(* Logix 5000 project; controller Demo_E300 vendor 1 type 14 code 164 rev 35.11; software revision 35.00 *)

TASK MainTask (continuous, watchdog 500 ms) : MainProgram

MODULES
   Local : vendor 1 type 14 code 164 (ICP 0, rev 35.11)
      Enet : 1756-EN2T (ICP 1, Ethernet 192.168.1.1, rev 11.1)   // Ethernet Card for E300 Modules
         Motor_0 : 193-ECM-ETR (Ethernet 192.168.1.10, rev 6.1, StandardDataDriven RPI 100 ms)
END_MODULES

TYPE Motor_Data :
STRUCT
   PB_Start : BOOL;
   PB_Stop : BOOL;
   Running : BOOL;
   Voltage : REAL;
   Current : REAL;
   Power : REAL;
   Overload_Trip : BOOL;
   Phase_LossTrip : BOOL;
   Ground_Fault_Current_Trip : BOOL;
   Stall_Trip : BOOL;
   Trip_Reset : BOOL;
   Load_Percent : REAL;
END_STRUCT
END_TYPE

ADD_ON_INSTRUCTION E300_SIM   (* revision 1.0, vendor Rockwell Automation Mexico *)
// Add On instruction to simulate an E300 operation
// Revision note:
// Initial Version
VAR_INPUT
   E300_Motor_Start : BOOL; {required}
   E300_Motor_Stop : BOOL; {required}
END_VAR
VAR_OUTPUT
   E300_Motor_Run : BOOL; {access Read Only, required}
END_VAR
VAR_IN_OUT
   InputE300INP : AB:E300:I:3; {required}
   ConfigE300CFG : AB:E300:C:3; {required}
END_VAR
VAR_INPUT
   E300_Load : REAL;
END_VAR
VAR_IN_OUT
   OutputE300OUT : AB:E300:O:1; {required}
END_VAR
VAR_INPUT
   E300_Simulate_OverloadTrip : BOOL; {required}
   E300_Simulate_PhaseLossTrip : BOOL;
   E300_Simulate_GroundFaultCurrentTrip : BOOL;
   E300_Simulate_StallTrip : BOOL;
   E300_Simulate_JamTrip : BOOL;
   E300_Simulate_UnderloadTrip : BOOL;
   E300_Simulate_CurrentImbalanceTrip : BOOL;
   E300_Simulate_L1UnderCurrentTrip : BOOL;
   E300_Simulate_L2UnderCurrentTrip : BOOL;
   E300_Simulate_L3UnderCurrentTrip : BOOL;
   E300_Simulate_L1OverCurrentTrip : BOOL;
   E300_Simulate_L2OverCurrentTrip : BOOL;
   E300_Simulate_L3OverCurrentTrip : BOOL;
   E300_Simulate_L1LineLossTrip : BOOL;
   E300_Simulate_L2LineLossTrip : BOOL;
   E300_Simulate_L3LineLossTrip : BOOL;
   Trip_Reset : BOOL; {required}
   E300_Percent_Load : REAL; {access None, required}
END_VAR
VAR
   E300_Timer_2 : TIMER := (PRE := 4000); {access None}
   E300_Timer_3 : TIMER := (PRE := 19000); {access None}
   E300_Speed : DINT; {access None}
   E300_Timer_1 : TIMER := (PRE := 100); {access None}
   E300_Random : REAL; {access None}
   E300_Factor_1 : REAL; {access None}
   E300_Factor_2 : REAL; {access None}
   E300_Factor_3 : REAL; {access None}
   E300_Current : REAL; {access None}
   E300_Current_Generated : REAL; {access None}
   E300_Seconds : TIMER := (PRE := 6000); {access None}
   E300_Minutes : COUNTER := (PRE := 60); {access None}
   E300_Hours : COUNTER := (PRE := 100000); {access None}
   E300_Torque_Generated : REAL; {access None}
   E300_HP_Generated : REAL; {access None}
   E300_FP_Generated : REAL; {access None}
   E300_Speed_Simulated : DINT; {access None}
   E300_Current_Scalated : DINT; {access None}
   E300_Curve_Amps : REAL[28]; {access None}
   E300_FGEN_AMPS : DINT; {access None}
   E300_Voltage_Generated : DINT; {access None}
   E300_Torque_Scalated : REAL; {access None}
   E300_Curve_Torque : REAL[28]; {access None}
   E300_FGEN_Torque : REAL; {access None}
   E300_Curve_FP : REAL[28]; {access None}
   E300_FGEN_PF : REAL; {access None}
END_VAR

ROUTINE Logic   (* ladder *)
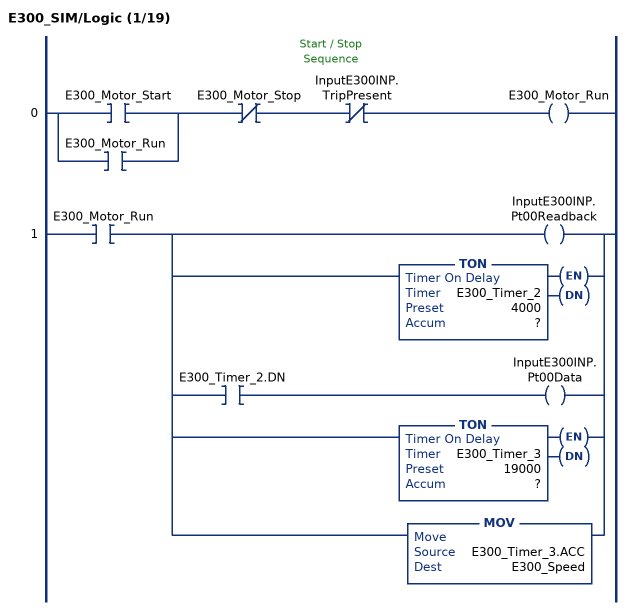
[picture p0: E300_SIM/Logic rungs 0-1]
   // Start / Stop
   // Sequence
   0: [XIC(E300_Motor_Start) ,XIC(E300_Motor_Run) ]XIO(E300_Motor_Stop)XIO(InputE300INP.TripPresent)OTE(E300_Motor_Run);
   1: XIC(E300_Motor_Run)[OTE(InputE300INP.Pt00Readback) ,TON(E300_Timer_2,?,?) ,XIC(E300_Timer_2.DN) OTE(InputE300INP.Pt00Data) ,TON(E300_Timer_3,?,?) ,MOV(E300_Timer_3.ACC,E300_Speed) ];
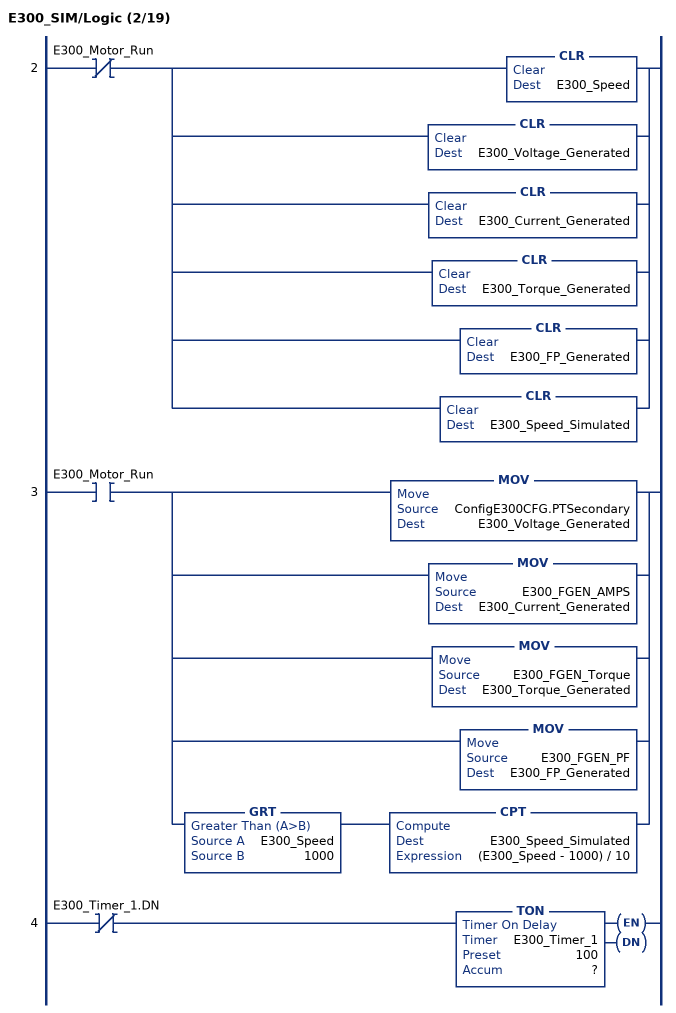
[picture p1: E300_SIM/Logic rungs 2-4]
   2: XIO(E300_Motor_Run)[CLR(E300_Speed) ,CLR(E300_Voltage_Generated) ,CLR(E300_Current_Generated) ,CLR(E300_Torque_Generated) ,CLR(E300_FP_Generated) ,CLR(E300_Speed_Simulated) ];
   3: XIC(E300_Motor_Run)[MOV(ConfigE300CFG.PTSecondary,E300_Voltage_Generated) ,MOV(E300_FGEN_AMPS,E300_Current_Generated) ,MOV(E300_FGEN_Torque,E300_Torque_Generated) ,MOV(E300_FGEN_PF,E300_FP_Generated) ,GRT(E300_Speed,1000) CPT(E300_Speed_Simulated,(E300_Speed - 1000) / 10) ];
   4: XIO(E300_Timer_1.DN)TON(E300_Timer_1,?,?);
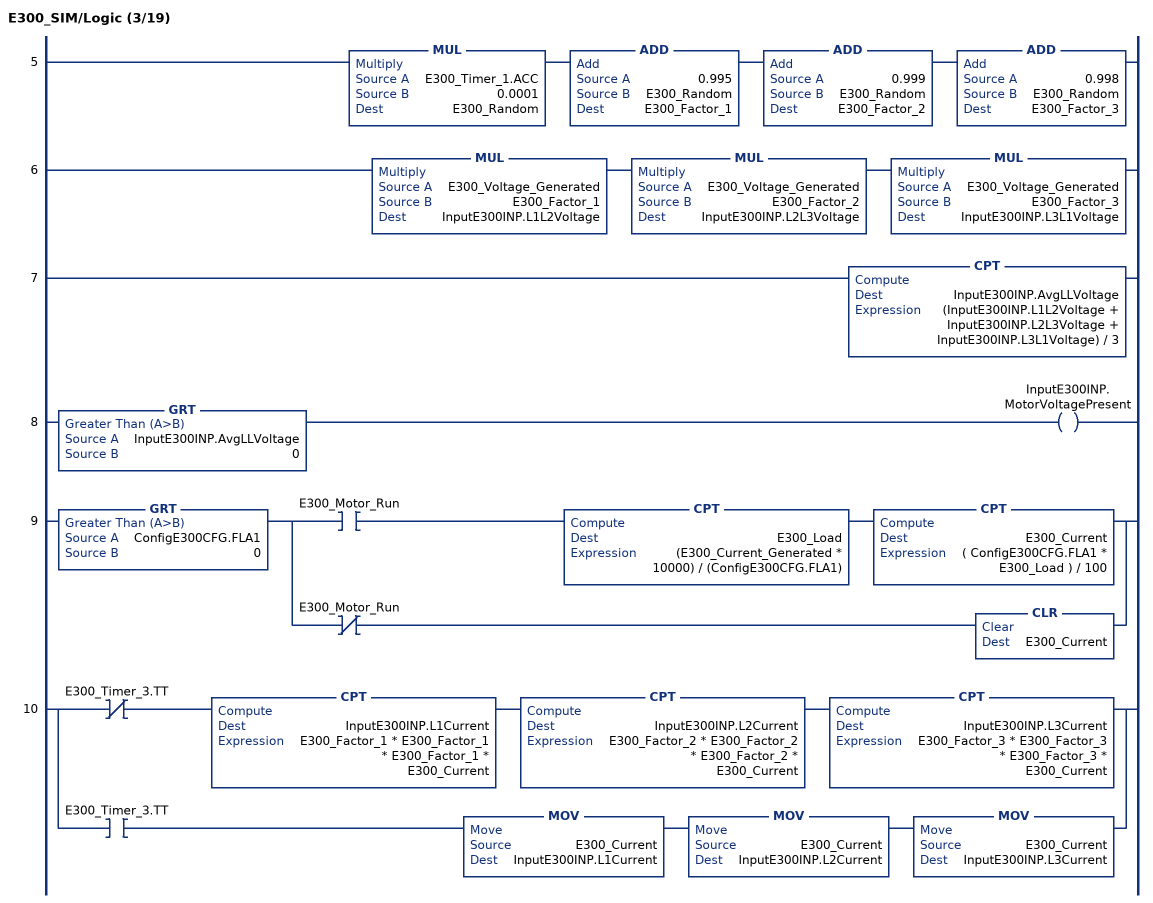
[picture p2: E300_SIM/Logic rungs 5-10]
   5: MUL(E300_Timer_1.ACC,0.0001,E300_Random)ADD(0.995,E300_Random,E300_Factor_1)ADD(0.999,E300_Random,E300_Factor_2)ADD(0.998,E300_Random,E300_Factor_3);
   6: MUL(E300_Voltage_Generated,E300_Factor_1,InputE300INP.L1L2Voltage)MUL(E300_Voltage_Generated,E300_Factor_2,InputE300INP.L2L3Voltage)MUL(E300_Voltage_Generated,E300_Factor_3,InputE300INP.L3L1Voltage);
   7: CPT(InputE300INP.AvgLLVoltage,(InputE300INP.L1L2Voltage + InputE300INP.L2L3Voltage + InputE300INP.L3L1Voltage) / 3);
   8: GRT(InputE300INP.AvgLLVoltage,0)OTE(InputE300INP.MotorVoltagePresent);
   9: GRT(ConfigE300CFG.FLA1,0)[XIC(E300_Motor_Run) CPT(E300_Load,(E300_Current_Generated * 10000) / (ConfigE300CFG.FLA1)) CPT(E300_Current,( ConfigE300CFG.FLA1 * E300_Load ) / 100) ,XIO(E300_Motor_Run) CLR(E300_Current) ];
   10: [XIO(E300_Timer_3.TT) CPT(InputE300INP.L1Current,E300_Factor_1 * E300_Factor_1 * E300_Factor_1 * E300_Current) CPT(InputE300INP.L2Current,E300_Factor_2 * E300_Factor_2 * E300_Factor_2 * E300_Current) CPT(InputE300INP.L3Current,E300_Factor_3 * E300_Factor_3 * E300_Factor_3 * E300_Current) ,XIC(E300_Timer_3.TT) MOV(E300_Current,InputE300INP.L1Current) MOV(E300_Current,InputE300INP.L2Current) MOV(E300_Current,InputE300INP.L3Current) ];
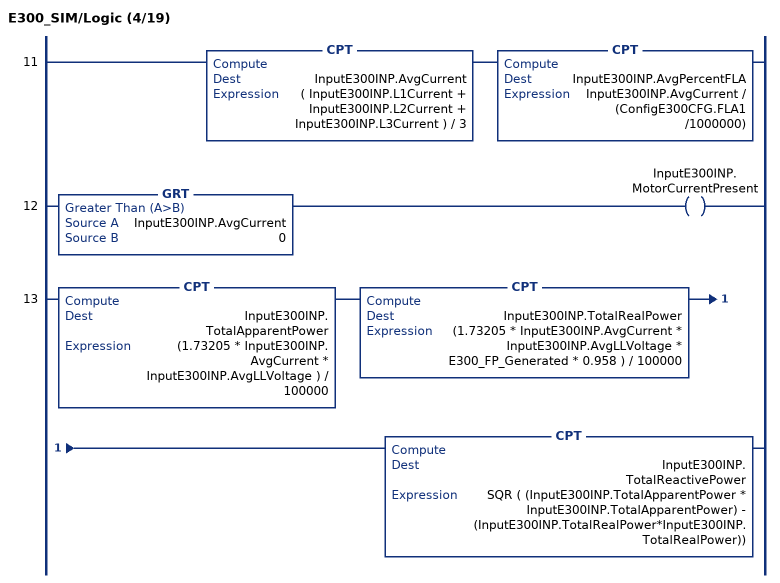
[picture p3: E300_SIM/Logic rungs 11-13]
   11: CPT(InputE300INP.AvgCurrent,( InputE300INP.L1Current + InputE300INP.L2Current + InputE300INP.L3Current ) / 3)CPT(InputE300INP.AvgPercentFLA,InputE300INP.AvgCurrent / (ConfigE300CFG.FLA1 /1000000));
   12: GRT(InputE300INP.AvgCurrent,0)OTE(InputE300INP.MotorCurrentPresent);
   13: CPT(InputE300INP.TotalApparentPower,(1.73205 * InputE300INP.AvgCurrent * InputE300INP.AvgLLVoltage ) / 100000)CPT(InputE300INP.TotalRealPower,(1.73205 * InputE300INP.AvgCurrent * InputE300INP.AvgLLVoltage * E300_FP_Generated * 0.958 ) / 100000)CPT(InputE300INP.TotalReactivePower,SQR ( (InputE300INP.TotalApparentPower * InputE300INP.TotalApparentPower) - (InputE300INP.TotalRealPower*InputE300INP.TotalRealPower)));
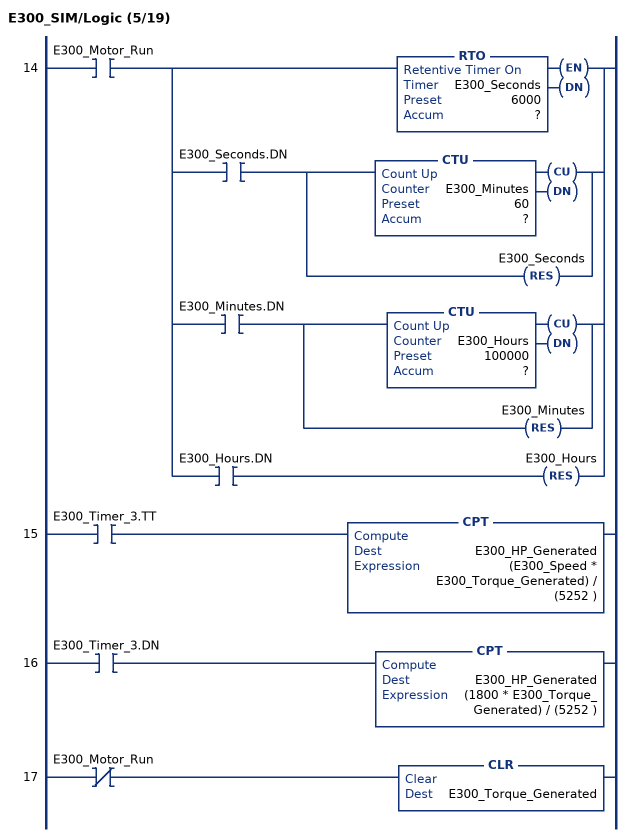
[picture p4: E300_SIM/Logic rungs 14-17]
   14: XIC(E300_Motor_Run)[RTO(E300_Seconds,?,?) ,XIC(E300_Seconds.DN) [CTU(E300_Minutes,?,?) ,RES(E300_Seconds) ] ,XIC(E300_Minutes.DN) [CTU(E300_Hours,?,?) ,RES(E300_Minutes) ] ,XIC(E300_Hours.DN) RES(E300_Hours) ];
   15: XIC(E300_Timer_3.TT)CPT(E300_HP_Generated,(E300_Speed * E300_Torque_Generated) / (5252 ));
   16: XIC(E300_Timer_3.DN)CPT(E300_HP_Generated,(1800 * E300_Torque_Generated) / (5252 ));
   17: XIO(E300_Motor_Run)CLR(E300_Torque_Generated);
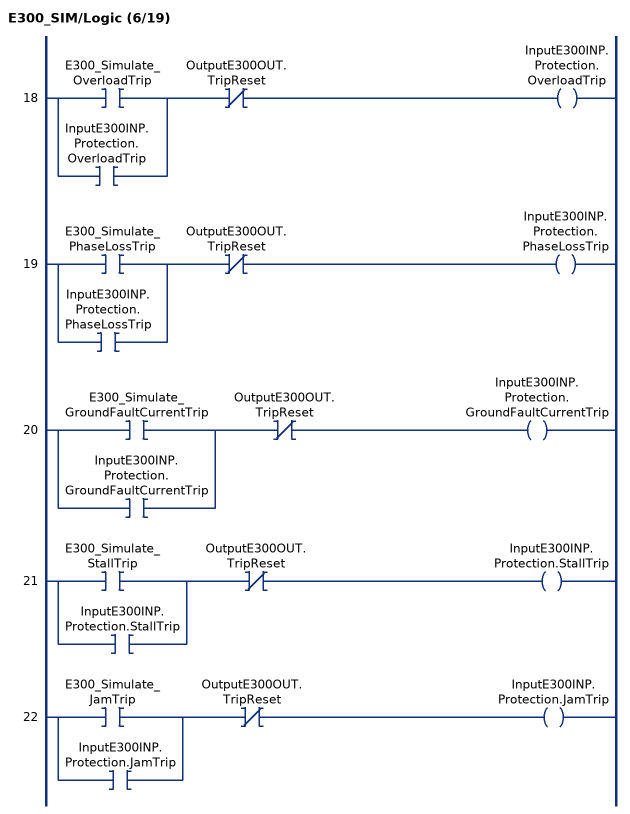
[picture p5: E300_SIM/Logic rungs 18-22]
   18: [XIC(E300_Simulate_OverloadTrip) ,XIC(InputE300INP.Protection.OverloadTrip) ]XIO(OutputE300OUT.TripReset)OTE(InputE300INP.Protection.OverloadTrip);
   19: [XIC(E300_Simulate_PhaseLossTrip) ,XIC(InputE300INP.Protection.PhaseLossTrip) ]XIO(OutputE300OUT.TripReset)OTE(InputE300INP.Protection.PhaseLossTrip);
   20: [XIC(E300_Simulate_GroundFaultCurrentTrip) ,XIC(InputE300INP.Protection.GroundFaultCurrentTrip) ]XIO(OutputE300OUT.TripReset)OTE(InputE300INP.Protection.GroundFaultCurrentTrip);
   21: [XIC(E300_Simulate_StallTrip) ,XIC(InputE300INP.Protection.StallTrip) ]XIO(OutputE300OUT.TripReset)OTE(InputE300INP.Protection.StallTrip);
   22: [XIC(E300_Simulate_JamTrip) ,XIC(InputE300INP.Protection.JamTrip) ]XIO(OutputE300OUT.TripReset)OTE(InputE300INP.Protection.JamTrip);
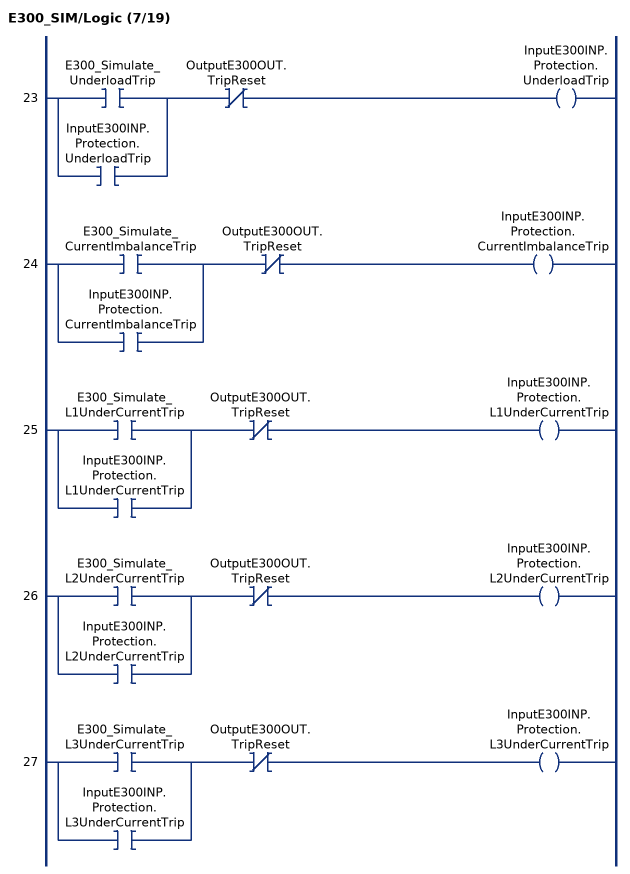
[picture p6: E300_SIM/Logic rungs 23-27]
   23: [XIC(E300_Simulate_UnderloadTrip) ,XIC(InputE300INP.Protection.UnderloadTrip) ]XIO(OutputE300OUT.TripReset)OTE(InputE300INP.Protection.UnderloadTrip);
   24: [XIC(E300_Simulate_CurrentImbalanceTrip) ,XIC(InputE300INP.Protection.CurrentImbalanceTrip) ]XIO(OutputE300OUT.TripReset)OTE(InputE300INP.Protection.CurrentImbalanceTrip);
   25: [XIC(E300_Simulate_L1UnderCurrentTrip) ,XIC(InputE300INP.Protection.L1UnderCurrentTrip) ]XIO(OutputE300OUT.TripReset)OTE(InputE300INP.Protection.L1UnderCurrentTrip);
   26: [XIC(E300_Simulate_L2UnderCurrentTrip) ,XIC(InputE300INP.Protection.L2UnderCurrentTrip) ]XIO(OutputE300OUT.TripReset)OTE(InputE300INP.Protection.L2UnderCurrentTrip);
   27: [XIC(E300_Simulate_L3UnderCurrentTrip) ,XIC(InputE300INP.Protection.L3UnderCurrentTrip) ]XIO(OutputE300OUT.TripReset)OTE(InputE300INP.Protection.L3UnderCurrentTrip);
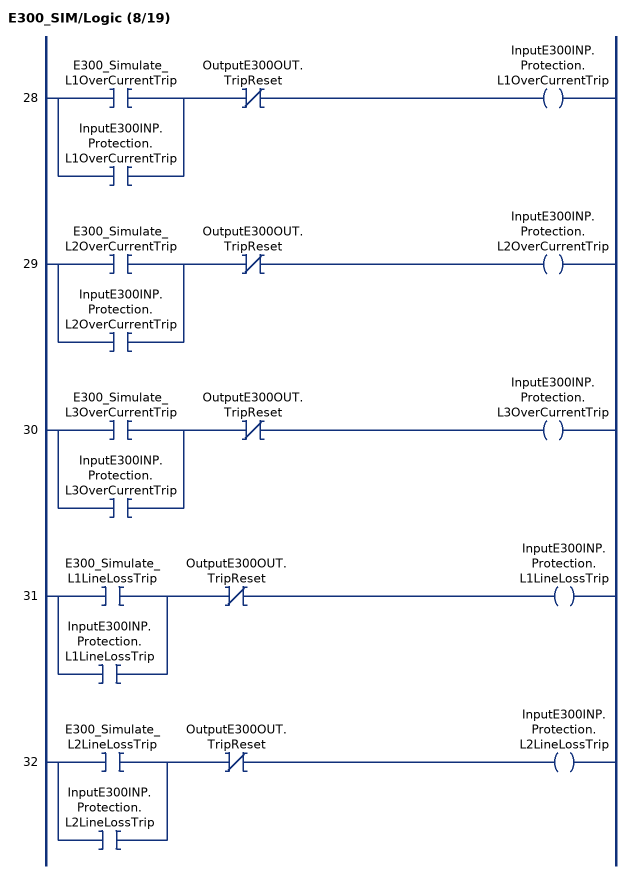
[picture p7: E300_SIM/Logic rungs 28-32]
   28: [XIC(E300_Simulate_L1OverCurrentTrip) ,XIC(InputE300INP.Protection.L1OverCurrentTrip) ]XIO(OutputE300OUT.TripReset)OTE(InputE300INP.Protection.L1OverCurrentTrip);
   29: [XIC(E300_Simulate_L2OverCurrentTrip) ,XIC(InputE300INP.Protection.L2OverCurrentTrip) ]XIO(OutputE300OUT.TripReset)OTE(InputE300INP.Protection.L2OverCurrentTrip);
   30: [XIC(E300_Simulate_L3OverCurrentTrip) ,XIC(InputE300INP.Protection.L3OverCurrentTrip) ]XIO(OutputE300OUT.TripReset)OTE(InputE300INP.Protection.L3OverCurrentTrip);
   31: [XIC(E300_Simulate_L1LineLossTrip) ,XIC(InputE300INP.Protection.L1LineLossTrip) ]XIO(OutputE300OUT.TripReset)OTE(InputE300INP.Protection.L1LineLossTrip);
   32: [XIC(E300_Simulate_L2LineLossTrip) ,XIC(InputE300INP.Protection.L2LineLossTrip) ]XIO(OutputE300OUT.TripReset)OTE(InputE300INP.Protection.L2LineLossTrip);
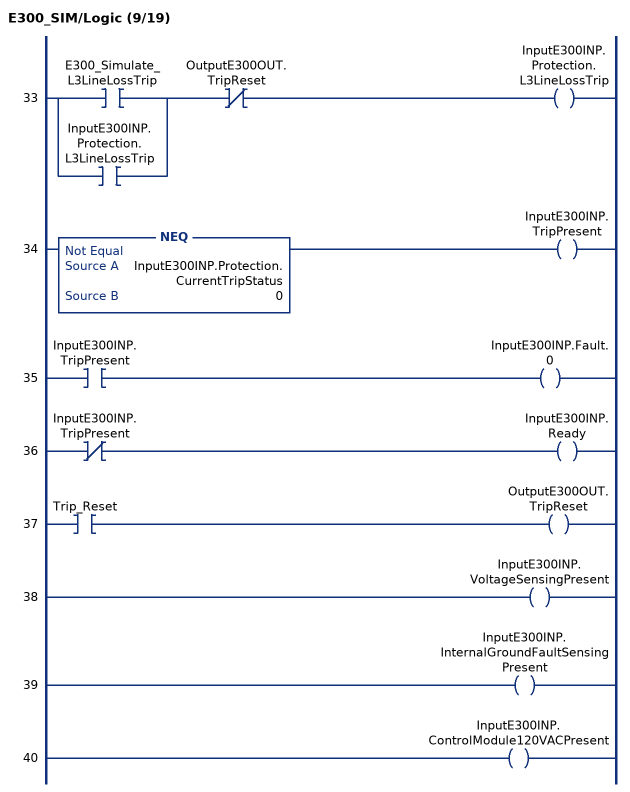
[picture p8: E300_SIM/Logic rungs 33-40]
   33: [XIC(E300_Simulate_L3LineLossTrip) ,XIC(InputE300INP.Protection.L3LineLossTrip) ]XIO(OutputE300OUT.TripReset)OTE(InputE300INP.Protection.L3LineLossTrip);
   34: NEQ(InputE300INP.Protection.CurrentTripStatus,0)OTE(InputE300INP.TripPresent);
   35: XIC(InputE300INP.TripPresent)OTE(InputE300INP.Fault.0);
   36: XIO(InputE300INP.TripPresent)OTE(InputE300INP.Ready);
   37: XIC(Trip_Reset)OTE(OutputE300OUT.TripReset);
   38: OTE(InputE300INP.VoltageSensingPresent);
   39: OTE(InputE300INP.InternalGroundFaultSensingPresent);
   40: OTE(InputE300INP.ControlModule120VACPresent);
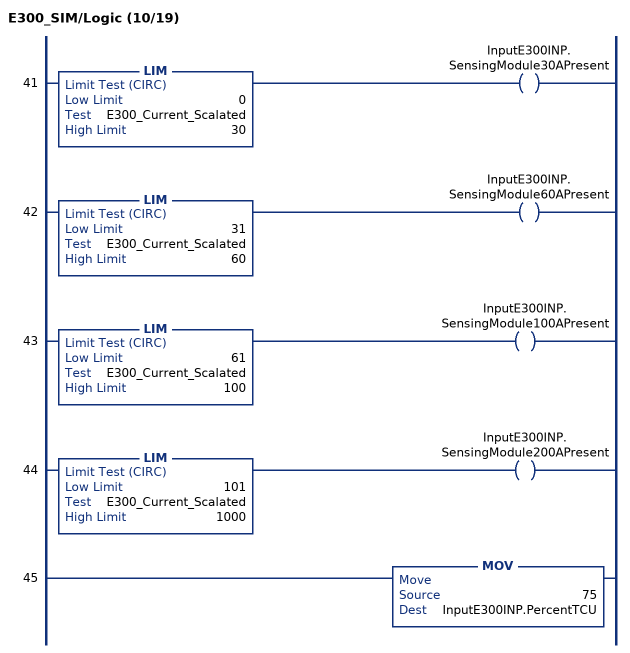
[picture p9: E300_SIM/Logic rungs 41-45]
   41: LIM(0,E300_Current_Scalated,30)OTE(InputE300INP.SensingModule30APresent);
   42: LIM(31,E300_Current_Scalated,60)OTE(InputE300INP.SensingModule60APresent);
   43: LIM(61,E300_Current_Scalated,100)OTE(InputE300INP.SensingModule100APresent);
   44: LIM(101,E300_Current_Scalated,1000)OTE(InputE300INP.SensingModule200APresent);
   45: MOV(75,InputE300INP.PercentTCU);
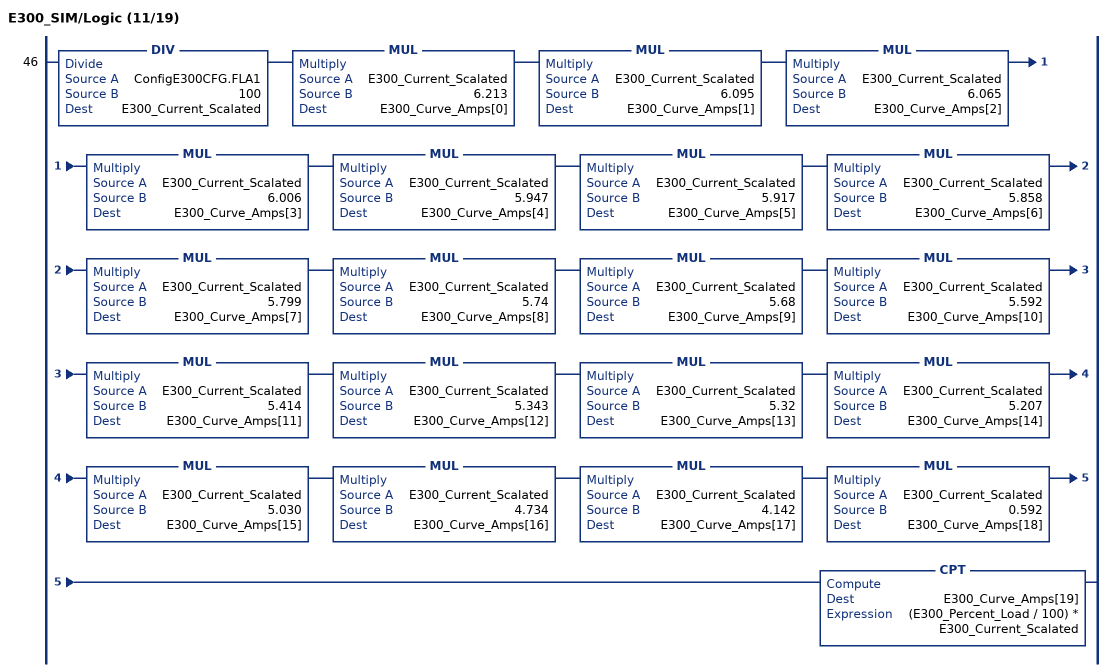
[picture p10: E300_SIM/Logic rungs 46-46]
   46: DIV(ConfigE300CFG.FLA1,100,E300_Current_Scalated)MUL(E300_Current_Scalated,6.213,E300_Curve_Amps[0])MUL(E300_Current_Scalated,6.095,E300_Curve_Amps[1])MUL(E300_Current_Scalated,6.065,E300_Curve_Amps[2])MUL(E300_Current_Scalated,6.006,E300_Curve_Amps[3])MUL(E300_Current_Scalated,5.947,E300_Curve_Amps[4])MUL(E300_Current_Scalated,5.917,E300_Curve_Amps[5])MUL(E300_Current_Scalated,5.858,E300_Curve_Amps[6])MUL(E300_Current_Scalated,5.799,E300_Curve_Amps[7])MUL(E300_Current_Scalated,5.74,E300_Curve_Amps[8])MUL(E300_Current_Scalated,5.68,E300_Curve_Amps[9])MUL(E300_Current_Scalated,5.592,E300_Curve_Amps[10])MUL(E300_Current_Scalated,5.414,E300_Curve_Amps[11])MUL(E300_Current_Scalated,5.343,E300_Curve_Amps[12])MUL(E300_Current_Scalated,5.32,E300_Curve_Amps[13])MUL(E300_Current_Scalated,5.207,E300_Curve_Amps[14])MUL(E300_Current_Scalated,5.030,E300_Curve_Amps[15])MUL(E300_Current_Scalated,4.734,E300_Curve_Amps[16])MUL(E300_Current_Scalated,4.142,E300_Curve_Amps[17])MUL(E300_Current_Scalated,0.592,E300_Curve_Amps[18])CPT(E300_Curve_Amps[19],(E300_Percent_Load / 100) * E300_Current_Scalated);
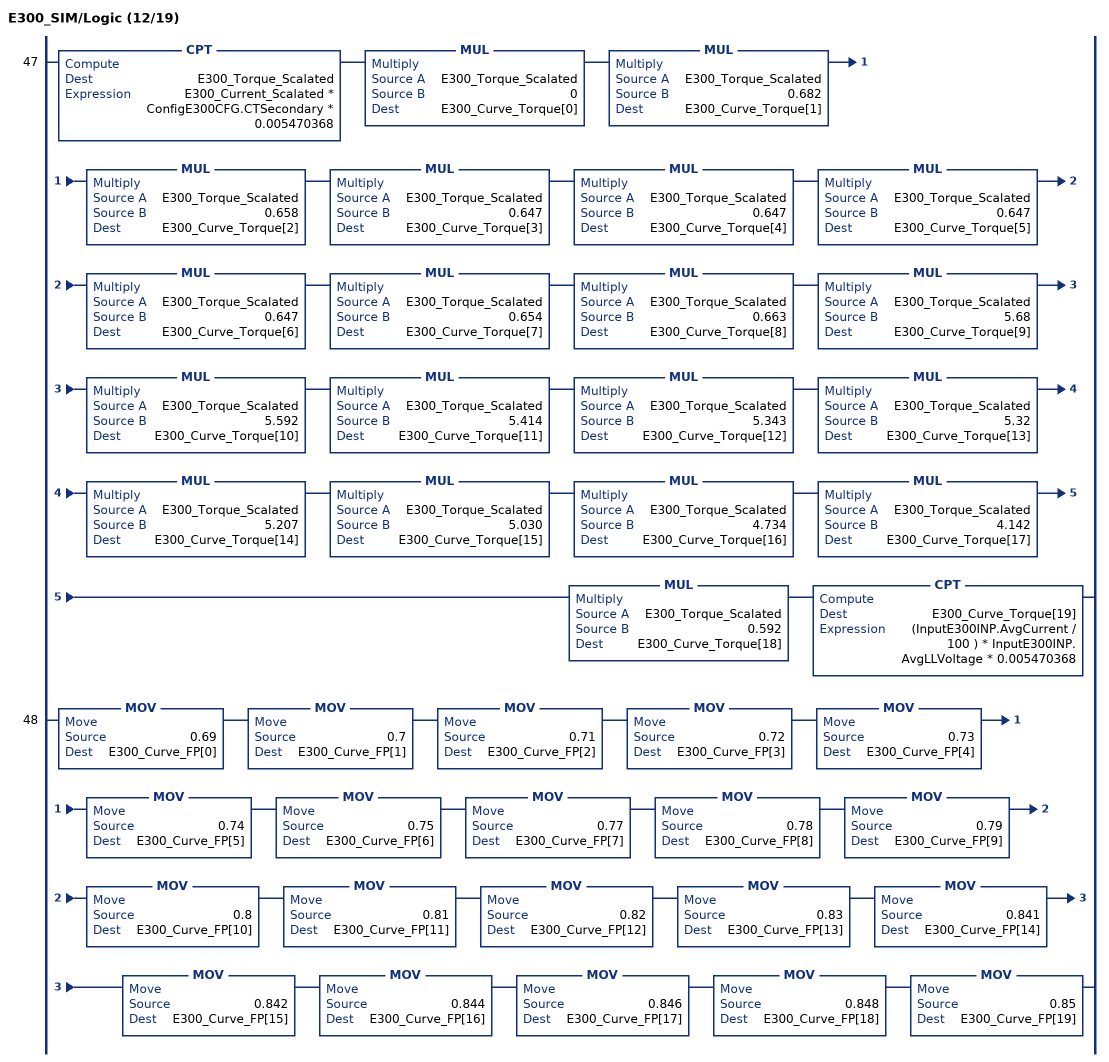
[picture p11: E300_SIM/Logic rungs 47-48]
   47: CPT(E300_Torque_Scalated,E300_Current_Scalated * ConfigE300CFG.CTSecondary * 0.005470368)MUL(E300_Torque_Scalated,0,E300_Curve_Torque[0])MUL(E300_Torque_Scalated,0.682,E300_Curve_Torque[1])MUL(E300_Torque_Scalated,0.658,E300_Curve_Torque[2])MUL(E300_Torque_Scalated,0.647,E300_Curve_Torque[3])MUL(E300_Torque_Scalated,0.647,E300_Curve_Torque[4])MUL(E300_Torque_Scalated,0.647,E300_Curve_Torque[5])MUL(E300_Torque_Scalated,0.647,E300_Curve_Torque[6])MUL(E300_Torque_Scalated,0.654,E300_Curve_Torque[7])MUL(E300_Torque_Scalated,0.663,E300_Curve_Torque[8])MUL(E300_Torque_Scalated,5.68,E300_Curve_Torque[9])MUL(E300_Torque_Scalated,5.592,E300_Curve_Torque[10])MUL(E300_Torque_Scalated,5.414,E300_Curve_Torque[11])MUL(E300_Torque_Scalated,5.343,E300_Curve_Torque[12])MUL(E300_Torque_Scalated,5.32,E300_Curve_Torque[13])MUL(E300_Torque_Scalated,5.207,E300_Curve_Torque[14])MUL(E300_Torque_Scalated,5.030,E300_Curve_Torque[15])MUL(E300_Torque_Scalated,4.734,E300_Curve_Torque[16])MUL(E300_Torque_Scalated,4.142,E300_Curve_Torque[17])MUL(E300_Torque_Scalated,0.592,E300_Curve_Torque[18])CPT(E300_Curve_Torque[19],(InputE300INP.AvgCurrent / 100 ) * InputE300INP.AvgLLVoltage * 0.005470368);
   48: MOV(0.69,E300_Curve_FP[0])MOV(0.7,E300_Curve_FP[1])MOV(0.71,E300_Curve_FP[2])MOV(0.72,E300_Curve_FP[3])MOV(0.73,E300_Curve_FP[4])MOV(0.74,E300_Curve_FP[5])MOV(0.75,E300_Curve_FP[6])MOV(0.77,E300_Curve_FP[7])MOV(0.78,E300_Curve_FP[8])MOV(0.79,E300_Curve_FP[9])MOV(0.8,E300_Curve_FP[10])MOV(0.81,E300_Curve_FP[11])MOV(0.82,E300_Curve_FP[12])MOV(0.83,E300_Curve_FP[13])MOV(0.841,E300_Curve_FP[14])MOV(0.842,E300_Curve_FP[15])MOV(0.844,E300_Curve_FP[16])MOV(0.846,E300_Curve_FP[17])MOV(0.848,E300_Curve_FP[18])MOV(0.85,E300_Curve_FP[19]);
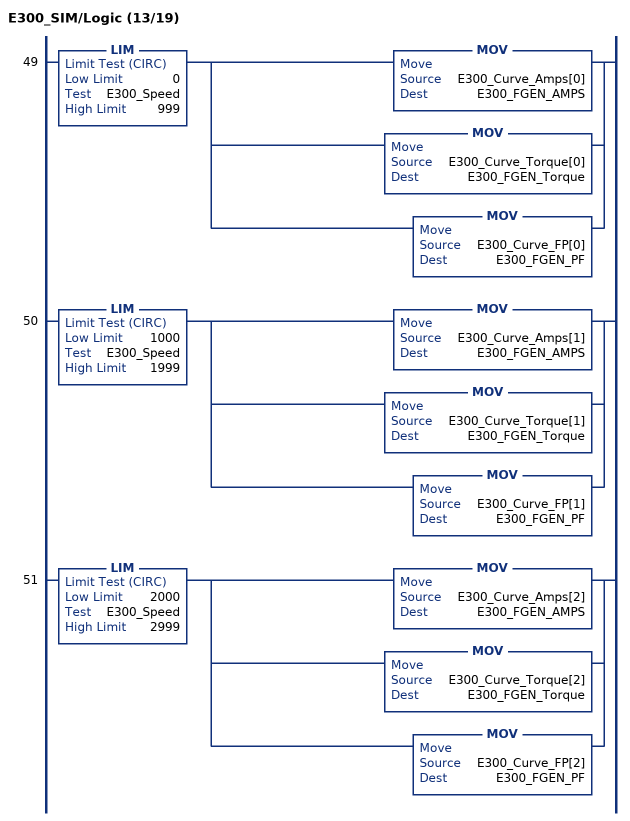
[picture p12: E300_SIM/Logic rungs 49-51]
   49: LIM(0,E300_Speed,999)[MOV(E300_Curve_Amps[0],E300_FGEN_AMPS) ,MOV(E300_Curve_Torque[0],E300_FGEN_Torque) ,MOV(E300_Curve_FP[0],E300_FGEN_PF) ];
   50: LIM(1000,E300_Speed,1999)[MOV(E300_Curve_Amps[1],E300_FGEN_AMPS) ,MOV(E300_Curve_Torque[1],E300_FGEN_Torque) ,MOV(E300_Curve_FP[1],E300_FGEN_PF) ];
   51: LIM(2000,E300_Speed,2999)[MOV(E300_Curve_Amps[2],E300_FGEN_AMPS) ,MOV(E300_Curve_Torque[2],E300_FGEN_Torque) ,MOV(E300_Curve_FP[2],E300_FGEN_PF) ];
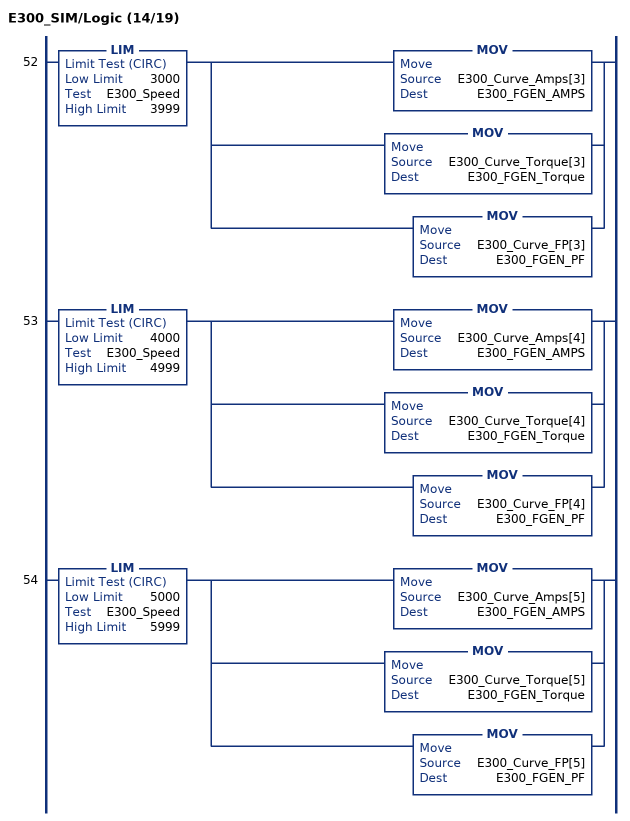
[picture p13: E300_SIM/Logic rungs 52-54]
   52: LIM(3000,E300_Speed,3999)[MOV(E300_Curve_Amps[3],E300_FGEN_AMPS) ,MOV(E300_Curve_Torque[3],E300_FGEN_Torque) ,MOV(E300_Curve_FP[3],E300_FGEN_PF) ];
   53: LIM(4000,E300_Speed,4999)[MOV(E300_Curve_Amps[4],E300_FGEN_AMPS) ,MOV(E300_Curve_Torque[4],E300_FGEN_Torque) ,MOV(E300_Curve_FP[4],E300_FGEN_PF) ];
   54: LIM(5000,E300_Speed,5999)[MOV(E300_Curve_Amps[5],E300_FGEN_AMPS) ,MOV(E300_Curve_Torque[5],E300_FGEN_Torque) ,MOV(E300_Curve_FP[5],E300_FGEN_PF) ];
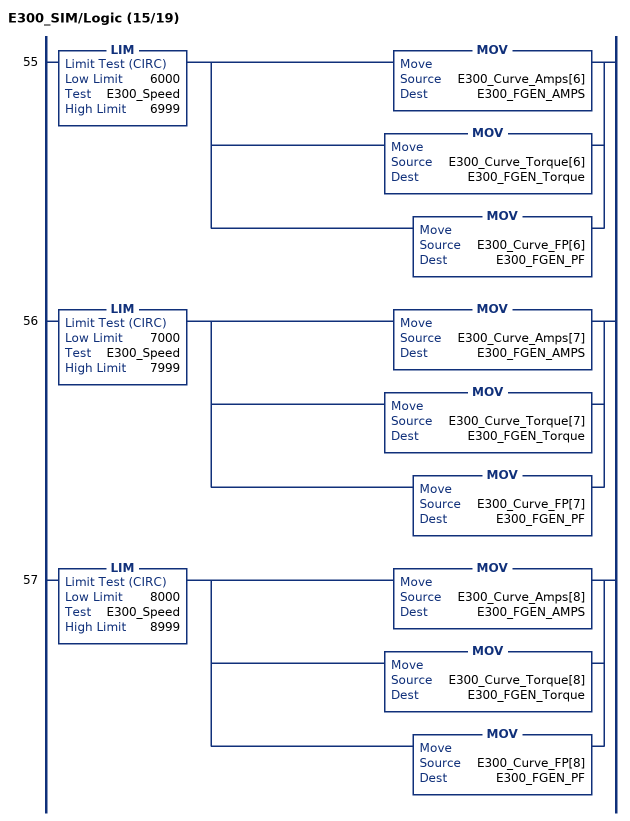
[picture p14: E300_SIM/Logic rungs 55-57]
   55: LIM(6000,E300_Speed,6999)[MOV(E300_Curve_Amps[6],E300_FGEN_AMPS) ,MOV(E300_Curve_Torque[6],E300_FGEN_Torque) ,MOV(E300_Curve_FP[6],E300_FGEN_PF) ];
   56: LIM(7000,E300_Speed,7999)[MOV(E300_Curve_Amps[7],E300_FGEN_AMPS) ,MOV(E300_Curve_Torque[7],E300_FGEN_Torque) ,MOV(E300_Curve_FP[7],E300_FGEN_PF) ];
   57: LIM(8000,E300_Speed,8999)[MOV(E300_Curve_Amps[8],E300_FGEN_AMPS) ,MOV(E300_Curve_Torque[8],E300_FGEN_Torque) ,MOV(E300_Curve_FP[8],E300_FGEN_PF) ];
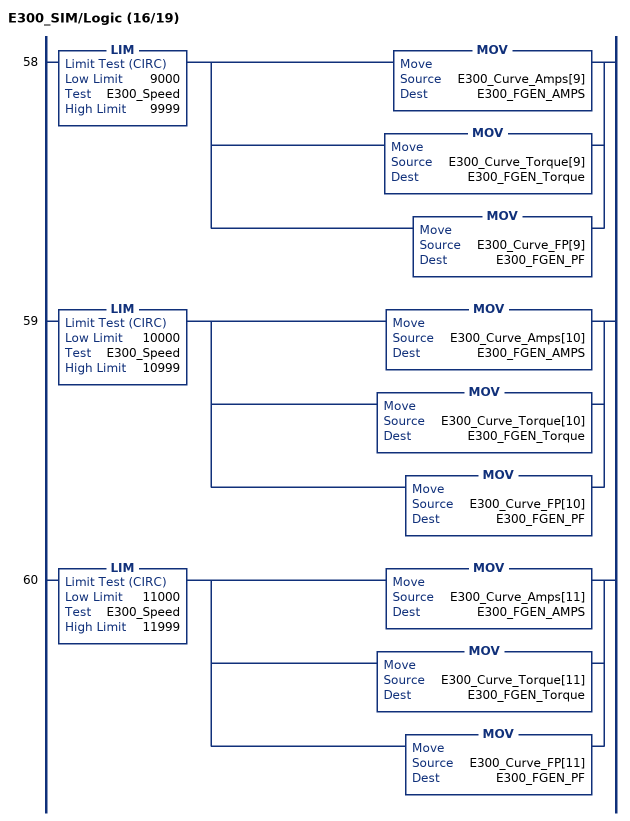
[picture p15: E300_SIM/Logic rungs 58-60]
   58: LIM(9000,E300_Speed,9999)[MOV(E300_Curve_Amps[9],E300_FGEN_AMPS) ,MOV(E300_Curve_Torque[9],E300_FGEN_Torque) ,MOV(E300_Curve_FP[9],E300_FGEN_PF) ];
   59: LIM(10000,E300_Speed,10999)[MOV(E300_Curve_Amps[10],E300_FGEN_AMPS) ,MOV(E300_Curve_Torque[10],E300_FGEN_Torque) ,MOV(E300_Curve_FP[10],E300_FGEN_PF) ];
   60: LIM(11000,E300_Speed,11999)[MOV(E300_Curve_Amps[11],E300_FGEN_AMPS) ,MOV(E300_Curve_Torque[11],E300_FGEN_Torque) ,MOV(E300_Curve_FP[11],E300_FGEN_PF) ];
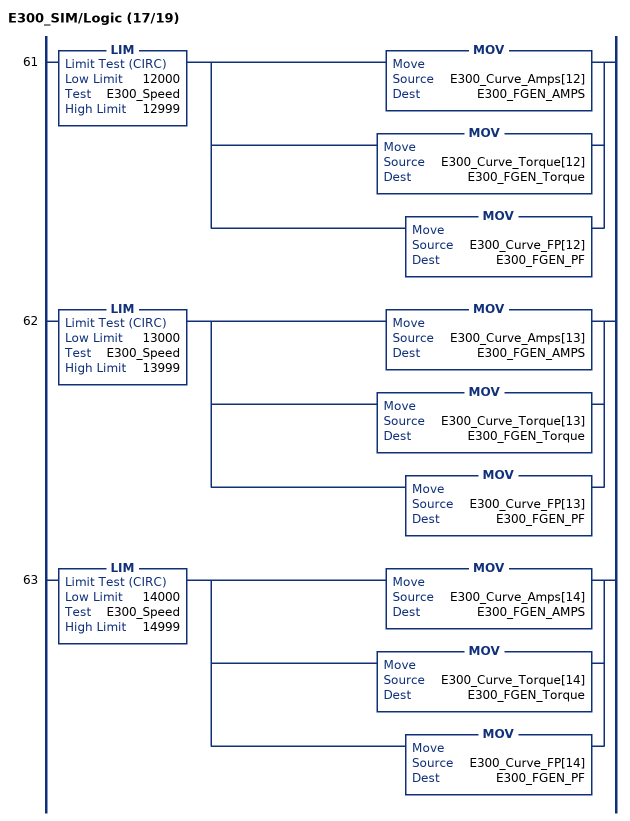
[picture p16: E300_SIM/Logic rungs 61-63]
   61: LIM(12000,E300_Speed,12999)[MOV(E300_Curve_Amps[12],E300_FGEN_AMPS) ,MOV(E300_Curve_Torque[12],E300_FGEN_Torque) ,MOV(E300_Curve_FP[12],E300_FGEN_PF) ];
   62: LIM(13000,E300_Speed,13999)[MOV(E300_Curve_Amps[13],E300_FGEN_AMPS) ,MOV(E300_Curve_Torque[13],E300_FGEN_Torque) ,MOV(E300_Curve_FP[13],E300_FGEN_PF) ];
   63: LIM(14000,E300_Speed,14999)[MOV(E300_Curve_Amps[14],E300_FGEN_AMPS) ,MOV(E300_Curve_Torque[14],E300_FGEN_Torque) ,MOV(E300_Curve_FP[14],E300_FGEN_PF) ];
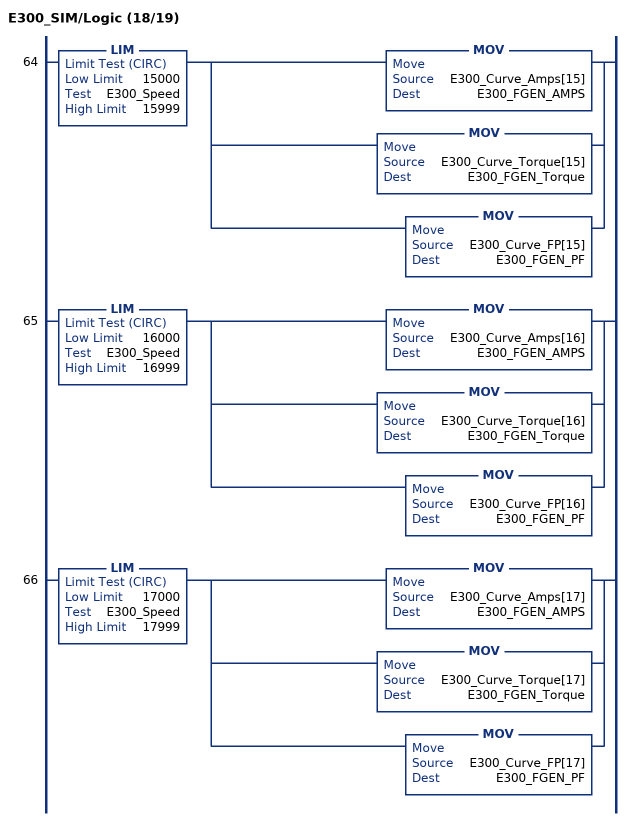
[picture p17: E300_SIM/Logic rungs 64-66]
   64: LIM(15000,E300_Speed,15999)[MOV(E300_Curve_Amps[15],E300_FGEN_AMPS) ,MOV(E300_Curve_Torque[15],E300_FGEN_Torque) ,MOV(E300_Curve_FP[15],E300_FGEN_PF) ];
   65: LIM(16000,E300_Speed,16999)[MOV(E300_Curve_Amps[16],E300_FGEN_AMPS) ,MOV(E300_Curve_Torque[16],E300_FGEN_Torque) ,MOV(E300_Curve_FP[16],E300_FGEN_PF) ];
   66: LIM(17000,E300_Speed,17999)[MOV(E300_Curve_Amps[17],E300_FGEN_AMPS) ,MOV(E300_Curve_Torque[17],E300_FGEN_Torque) ,MOV(E300_Curve_FP[17],E300_FGEN_PF) ];
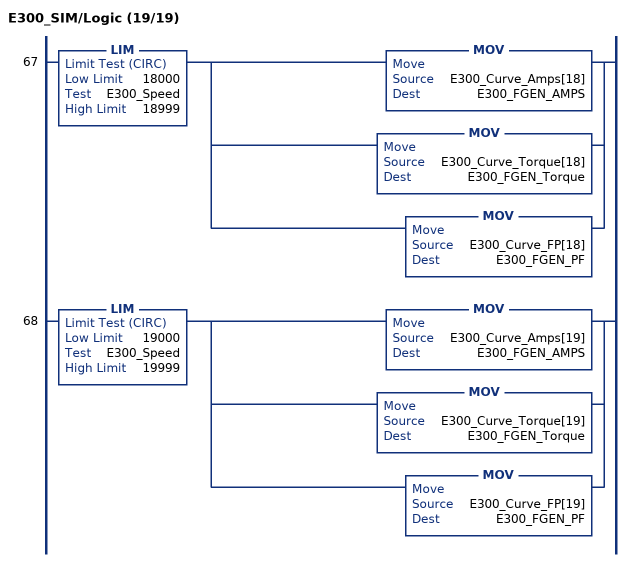
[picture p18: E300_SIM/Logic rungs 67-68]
   67: LIM(18000,E300_Speed,18999)[MOV(E300_Curve_Amps[18],E300_FGEN_AMPS) ,MOV(E300_Curve_Torque[18],E300_FGEN_Torque) ,MOV(E300_Curve_FP[18],E300_FGEN_PF) ];
   68: LIM(19000,E300_Speed,19999)[MOV(E300_Curve_Amps[19],E300_FGEN_AMPS) ,MOV(E300_Curve_Torque[19],E300_FGEN_Torque) ,MOV(E300_Curve_FP[19],E300_FGEN_PF) ];
END_ROUTINE
END_ADD_ON_INSTRUCTION

VAR_GLOBAL   (* controller tags *)
   Current : REAL;
   E300 : E300_SIM;
   Real_Power : REAL;
   Voltage : REAL;
END_VAR

PROGRAM MainProgram   (* main routine MainRoutine *)

ROUTINE MainRoutine   (* ladder *)
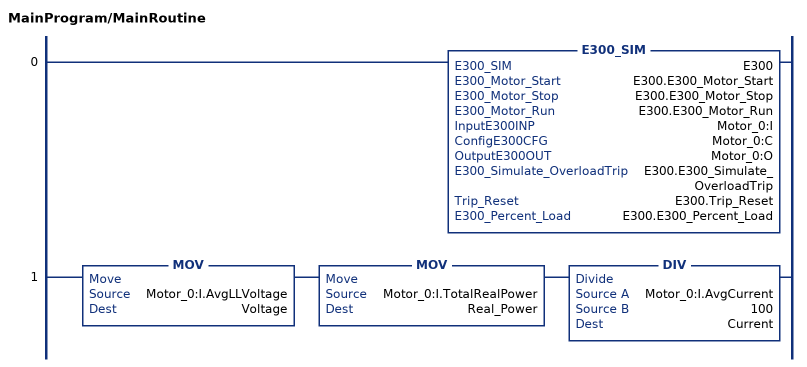
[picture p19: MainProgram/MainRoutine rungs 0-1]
   0: E300_SIM(E300,E300.E300_Motor_Start,E300.E300_Motor_Stop,E300.E300_Motor_Run,Motor_0:I,Motor_0:C,Motor_0:O,E300.E300_Simulate_OverloadTrip,E300.Trip_Reset,E300.E300_Percent_Load);
   1: MOV(Motor_0:I.AvgLLVoltage,Voltage)MOV(Motor_0:I.TotalRealPower,Real_Power)DIV(Motor_0:I.AvgCurrent,100,Current);
END_ROUTINE
END_PROGRAM
